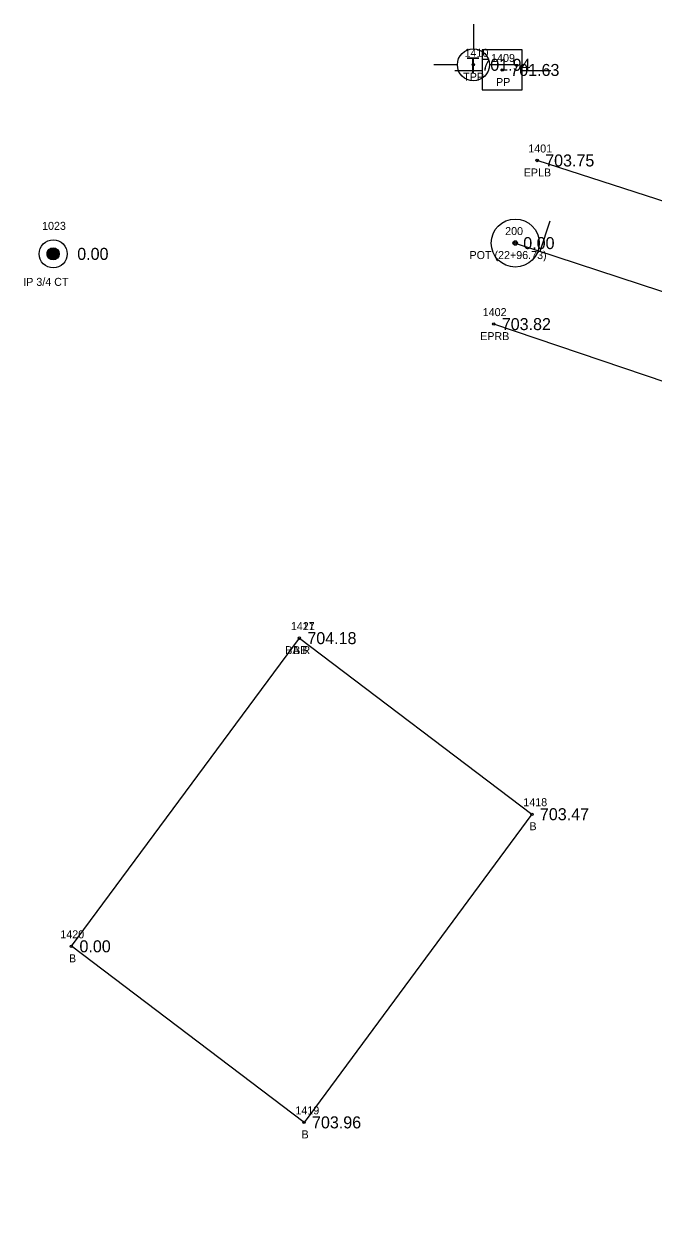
# Model space of a CAD drawing. Extents: x 1655137 to 1657928, y 1003994 to 1005407.
# Drawn here: x 1655640.2 to 1655718.8, y 1004724 to 1004875.1 of the extents above; entities that cross this region are included whole.
import ezdxf

# ---------------------------------------------------------------- set-up
doc = ezdxf.new("R2010")
doc.units = 0
for name, color, linetype in [('RD_EX_Bldg', 7, 'Continuous'), ('RD_EX_Bldg_txCode', 7, 'Continuous'), ('RD_EX_DV_Prop_txCode', 7, 'Continuous'), ('RD_EX_DV_PropPin', 7, 'Continuous'), ('RD_EX_Road', 7, 'Continuous'), ('RD_EX_Road_txCode', 7, 'Continuous'), ('RD_EX_TX_Bldg_ELEV', 7, 'Continuous'), ('RD_EX_TX_DV_Prop_ELEV', 7, 'Continuous'), ('RD_EX_TX_Road_ELEV', 7, 'Continuous'), ('RD_EX_TX_UT_ELEV', 7, 'Continuous'), ('RD_EX_UT', 7, 'Continuous'), ('RD_EX_UT_txCode', 7, 'Continuous'), ('RD_HC_Cl', 7, 'Continuous'), ('RD_HC_Data', 7, 'Continuous'), ('RD_HC_Data_Tic', 7, 'Continuous'), ('RD_HC_Survey_ELEV', 7, 'Continuous'), ('RD_HC_txCode', 7, 'Continuous'), ('RD_SMD_Locator', 7, 'Continuous')]:
    doc.layers.add(name, color=color, linetype=linetype)

msp = doc.modelspace()

# ---------------------------------------------------------------- linework, layer by layer
at = {"layer": 'RD_EX_Bldg'}
msp.add_lwpolyline([(1655674.55, 1004798.41), (1655703.59, 1004776.41), (1655675.13, 1004737.9), (1655646.09, 1004759.9), (1655674.55, 1004798.41)], dxfattribs=at)
at = {"layer": 'RD_EX_DV_PropPin'}
for p, q in [((1655643.07, 1004846.23), (1655643.07, 1004846.63)), ((1655643.11, 1004846.13), (1655643.11, 1004846.73)), ((1655643.14, 1004846.06), (1655643.14, 1004846.8)), ((1655643.18, 1004846), (1655643.18, 1004846.86)), ((1655643.21, 1004845.96), (1655643.21, 1004846.9)), ((1655643.25, 1004845.91), (1655643.25, 1004846.94)), ((1655643.28, 1004845.88), (1655643.28, 1004846.98)), ((1655643.32, 1004845.85), (1655643.32, 1004847.01)), ((1655643.35, 1004845.82), (1655643.35, 1004847.04)), ((1655643.39, 1004845.8), (1655643.39, 1004847.06)), ((1655643.42, 1004845.77), (1655643.42, 1004847.09)), ((1655643.46, 1004845.75), (1655643.46, 1004847.11)), ((1655643.49, 1004845.74), (1655643.49, 1004847.12)), ((1655643.53, 1004845.72), (1655643.53, 1004847.14)), ((1655643.56, 1004845.71), (1655643.56, 1004847.15)), ((1655643.6, 1004845.7), (1655643.6, 1004847.16)), ((1655643.63, 1004845.69), (1655643.63, 1004847.17)), ((1655643.67, 1004845.68), (1655643.67, 1004847.18)), ((1655643.7, 1004845.68), (1655643.7, 1004847.18)), ((1655643.74, 1004845.67), (1655643.74, 1004847.19)), ((1655643.77, 1004845.67), (1655643.77, 1004847.19)), ((1655643.81, 1004845.67), (1655643.81, 1004847.19)), ((1655643.84, 1004845.67), (1655643.84, 1004847.19)), ((1655643.88, 1004845.67), (1655643.88, 1004847.19)), ((1655643.91, 1004845.68), (1655643.91, 1004847.18)), ((1655643.95, 1004845.68), (1655643.95, 1004847.18)), ((1655643.98, 1004845.69), (1655643.98, 1004847.17)), ((1655644.02, 1004845.7), (1655644.02, 1004847.16)), ((1655644.05, 1004845.71), (1655644.05, 1004847.15)), ((1655644.09, 1004845.72), (1655644.09, 1004847.14)), ((1655644.12, 1004845.74), (1655644.12, 1004847.12)), ((1655644.16, 1004845.75), (1655644.16, 1004847.11)), ((1655644.19, 1004845.77), (1655644.19, 1004847.09)), ((1655644.23, 1004845.8), (1655644.23, 1004847.06)), ((1655644.26, 1004845.82), (1655644.26, 1004847.04)), ((1655644.3, 1004845.85), (1655644.3, 1004847.01)), ((1655644.33, 1004845.88), (1655644.33, 1004846.98)), ((1655644.37, 1004845.91), (1655644.37, 1004846.94)), ((1655644.4, 1004845.96), (1655644.4, 1004846.9)), ((1655644.44, 1004846), (1655644.44, 1004846.86)), ((1655644.47, 1004846.06), (1655644.47, 1004846.8)), ((1655644.51, 1004846.13), (1655644.51, 1004846.73)), ((1655644.54, 1004846.23), (1655644.54, 1004846.63))]:
    msp.add_line(p, q, dxfattribs=at)
for radius in [1.75, 0.761]:
    msp.add_circle((1655643.81, 1004846.43), radius, dxfattribs=at)
at = {"layer": 'RD_EX_Road'}
for points in [[(1656365.12, 1004639.99), (1656336.04, 1004649.34), (1656302.55, 1004660.37), (1656279.15, 1004668.23), (1656240.07, 1004681.05), (1656188.23, 1004698.03), (1656166.72, 1004705.51), (1656141.16, 1004714.06), (1656093.11, 1004730.11), (1656044.16, 1004746.75), (1655996.36, 1004762.45), (1655947.2, 1004778.68), (1655899.09, 1004794.03), (1655850.62, 1004809.99), (1655801.91, 1004826.1), (1655753.09, 1004842.31), (1655704.25, 1004858.1)], [(1656358.5, 1004619.83), (1656328.78, 1004629.48), (1656280.77, 1004645.39), (1656247.66, 1004656.11), (1656244.5, 1004656.52), (1656222.03, 1004663.57), (1656217.65, 1004665.96), (1656183.42, 1004677.32), (1656134.59, 1004693.72), (1656086.19, 1004709.75), (1656037.58, 1004726.13), (1655989.57, 1004741.99), (1655940.62, 1004757.88), (1655892.37, 1004773.61), (1655843.48, 1004789.36), (1655805.73, 1004801.4), (1655779.22, 1004810.43), (1655768.8, 1004813.1), (1655744.59, 1004822.13), (1655698.83, 1004837.65)]]:
    msp.add_lwpolyline(points, dxfattribs=at)
at = {"layer": 'RD_EX_UT'}
for p, q in [((1655696.28, 1004875.13), (1655696.28, 1004872.06)), ((1655702.38, 1004871.92), (1655697.38, 1004871.92)), ((1655697.38, 1004871.92), (1655697.38, 1004866.92)), ((1655702.38, 1004866.92), (1655702.38, 1004871.92)), ((1655691.35, 1004870.08), (1655694.28, 1004870.08)), ((1655693.95, 1004869.36), (1655697.42, 1004869.36)), ((1655698.28, 1004870.08), (1655701.35, 1004870.08)), ((1655702.31, 1004869.36), (1655705.95, 1004869.36)), ((1655697.38, 1004866.92), (1655702.38, 1004866.92))]:
    msp.add_line(p, q, dxfattribs=at)
msp.add_circle((1655696.28, 1004870.06), 2, dxfattribs=at)
at = {"layer": 'RD_HC_Cl'}
msp.add_line((1655701.51, 1004847.78), (1656069.26, 1004726.84), dxfattribs=at)
at = {"layer": 'RD_HC_Data'}
for radius in [3, 0.282]:
    msp.add_circle((1655701.51, 1004847.78), radius, dxfattribs=at)
at = {"layer": 'RD_HC_Data_Tic'}
msp.add_line((1655704.61, 1004846.75), (1655705.86, 1004850.55), dxfattribs=at)
at = {"layer": 'RD_SMD_Locator'}
for centre in [(1655696.28, 1004870.06), (1655699.89, 1004869.41), (1655704.25, 1004858.1), (1655643.81, 1004846.43), (1655701.51, 1004847.78), (1655698.83, 1004837.65), (1655674.55, 1004798.41), (1655674.55, 1004798.41), (1655703.59, 1004776.41), (1655646.09, 1004759.9), (1655675.13, 1004737.9)]:
    msp.add_circle(centre, 0.15, dxfattribs=at)

# ---------------------------------------------------------------- texts
at = {"layer": 'RD_EX_Bldg_txCode'}
for s, p in [('1421', (1655673.49, 1004799.41)), ('1417', (1655673.49, 1004799.41)), ('BA R', (1655672.79, 1004796.41)), ('BB', (1655673.77, 1004796.41)), ('1418', (1655702.52, 1004777.41)), ('B', (1655703.28, 1004774.41)), ('1420', (1655644.7, 1004760.9)), ('B', (1655645.78, 1004757.9)), ('1419', (1655674.06, 1004738.9)), ('B', (1655674.82, 1004735.9))]:
    msp.add_text(s, height=1, dxfattribs=at).set_placement(p)
at = {"layer": 'RD_EX_DV_Prop_txCode'}
for s, p in [('1023', (1655642.42, 1004849.43)), ('IP 3/4 CT', (1655640.07, 1004842.43))]:
    msp.add_text(s, height=1, dxfattribs=at).set_placement(p)
at = {"layer": 'RD_EX_Road_txCode'}
for s, p in [('1401', (1655703.14, 1004859.1)), ('EPLB', (1655702.57, 1004856.1)), ('1402', (1655697.45, 1004838.65)), ('EPRB', (1655697.13, 1004835.65))]:
    msp.add_text(s, height=1, dxfattribs=at).set_placement(p)
at = {"layer": 'RD_EX_TX_Bldg_ELEV'}
for s, p in [('704.18', (1655675.55, 1004797.66)), ('704.18', (1655675.55, 1004797.66)), ('703.47', (1655704.59, 1004775.66)), ('0.00', (1655647.09, 1004759.15)), ('703.96', (1655676.13, 1004737.15))]:
    msp.add_text(s, height=1.5, dxfattribs=at).set_placement(p)
at = {"layer": 'RD_EX_TX_DV_Prop_ELEV'}
msp.add_text('0.00', height=1.5, dxfattribs=at).set_placement((1655646.81, 1004845.68))
at = {"layer": 'RD_EX_TX_Road_ELEV'}
for s, p in [('703.75', (1655705.25, 1004857.35)), ('703.82', (1655699.83, 1004836.9))]:
    msp.add_text(s, height=1.5, dxfattribs=at).set_placement(p)
at = {"layer": 'RD_EX_TX_UT_ELEV'}
msp.add_text('701.94', height=1.5, dxfattribs=at).set_placement((1655697.28, 1004869.31))
at = {"layer": 'RD_EX_UT'}
msp.add_text('T', height=2, dxfattribs=at).set_placement((1655695.43, 1004869.01))
at = {"layer": 'RD_EX_UT_txCode'}
for s, p in [('1410', (1655695.18, 1004871.06)), ('1409', (1655698.5, 1004870.41)), ('TPP', (1655695.01, 1004868.06)), ('PP', (1655699.11, 1004867.41))]:
    msp.add_text(s, height=1, dxfattribs=at).set_placement(p)
at = {"layer": 'RD_HC_Survey_ELEV'}
for s, p in [('701.63', (1655700.89, 1004868.66)), ('0.00', (1655702.51, 1004847.03))]:
    msp.add_text(s, height=1.5, dxfattribs=at).set_placement(p)
at = {"layer": 'RD_HC_txCode'}
for s, p in [('200', (1655700.25, 1004848.78)), ('POT (22+96.73)', (1655695.8, 1004845.78))]:
    msp.add_text(s, height=1, dxfattribs=at).set_placement(p)

doc.saveas('drawing.dxf')
